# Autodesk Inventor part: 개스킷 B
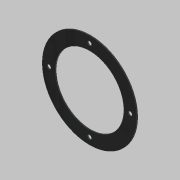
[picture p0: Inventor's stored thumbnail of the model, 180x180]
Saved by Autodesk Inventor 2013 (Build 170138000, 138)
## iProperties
Created: 2019-02
Part Number: 개스킷 B
Material: 고무
Document SubType Name: Modeling
Designer: mduedu
Density: 0.93 g/cm^3
Mass: 3.77481 g
Surface Area: 87.4305 cm^2
Volume: 4.05894 cm^3
Author: mduedu
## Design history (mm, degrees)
sketch "스케치1"
  geometry: C1 r 52.5 at (0, 0); C2 r 38 at (0, 0); 1 further point
  constraints: 2 centre point, 2 coincident
  dimensions: "d0" = 105 diameter of C1; "d1" = 76 diameter of C2
extrude "돌출1" new body sketch "스케치1" distance "d2" = 1; taper "d3" = 0 deg
sketch "스케치2" dims "d4" = 90
  geometry: 3 further points
  constraints: 2 vertical alignment, 1 coincident, 2 other
hole "구멍1" sketch "스케치2" at (0, 45) diameter "d5" = 4.5; stored, may be unused: countersink angle "d9" = 90 deg, drill point angle "d11" = 118 deg; dims "d6" = 6, "d7" = 4, "d8" = 2, "d10" = 8
node "솔리드1"
pattern_circular "원형 패턴1" dims angle "d13" = 360 deg
